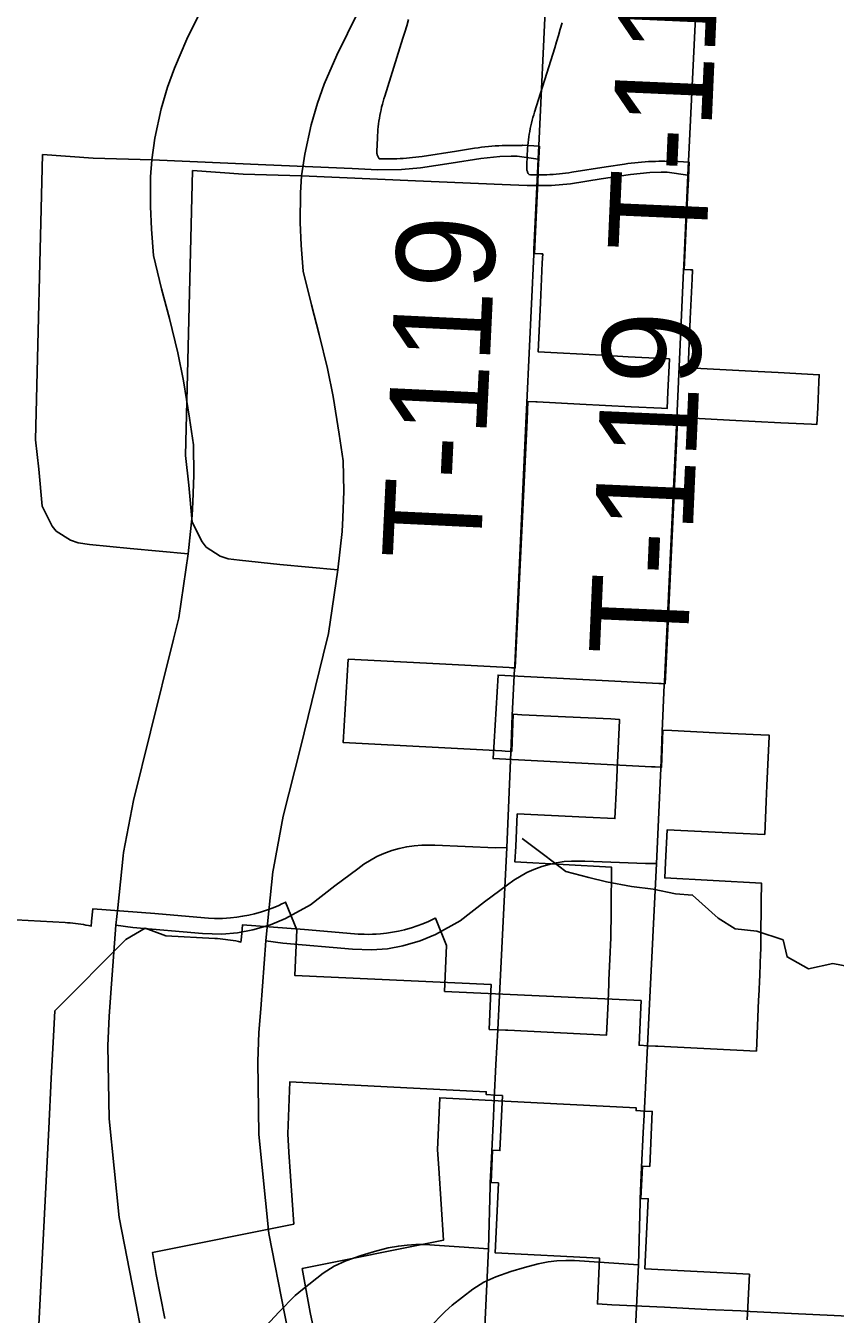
# Model space of a CAD drawing. Extents: x -38.2 to 41.9, y -4 to 24.9.
# Drawn here: x 6.18 to 6.647, y 16.76 to 17.504 of the extents above; entities that cross this region are included whole.
import ezdxf

# ---------------------------------------------------------------- set-up
doc = ezdxf.new("R2010")
doc.units = 0
for name, color, linetype in [('Default', 7, 'Continuous'), ('GM_X_County_Road', 7, 'Continuous'), ('GM_X_Minor_River', 7, 'Continuous'), ('GM_X_State_Location', 7, 'Continuous'), ('GM_X_Township_Road', 7, 'Continuous'), ('GM_X_Township_Road_Text', 7, 'Continuous')]:
    doc.layers.add(name, color=color, linetype=linetype)

msp = doc.modelspace()

# ---------------------------------------------------------------- linework, layer by layer
at = {"layer": 'Default'}
for points in [[(6.4011, 17.5072), (6.40004, 17.5036), (6.39895, 17.50001), (6.39783, 17.49642), (6.38727, 17.46302), (6.38679, 17.46145), (6.38633, 17.45987), (6.38591, 17.45829), (6.38551, 17.45669), (6.38514, 17.45509), (6.3848, 17.45348), (6.38449, 17.45187), (6.38421, 17.45025), (6.38395, 17.44863), (6.38373, 17.447), (6.38353, 17.44537), (6.38337, 17.44373), (6.38323, 17.4421), (6.38312, 17.44046), (6.38304, 17.43882), (6.38274, 17.43124), (6.38274, 17.43081), (6.38282, 17.42997), (6.38289, 17.42955), (6.383, 17.42914), (6.38313, 17.42874), (6.38329, 17.42835), (6.38347, 17.42796), (6.38368, 17.42759), (6.38391, 17.42724), (6.38417, 17.4269), (6.38489, 17.42687), (6.38566, 17.42684), (6.38667, 17.42681), (6.38697, 17.42681), (6.3888, 17.42678), (6.39063, 17.42678), (6.39246, 17.4268), (6.39428, 17.42686), (6.39611, 17.42694), (6.39794, 17.42704), (6.39977, 17.42718), (6.40159, 17.42734), (6.40341, 17.42753), (6.40523, 17.42774), (6.40704, 17.42798), (6.40885, 17.42825), (6.42869, 17.43134), (6.43917, 17.43297), (6.44114, 17.43326), (6.44313, 17.43352), (6.44511, 17.43376), (6.4471, 17.43397), (6.44909, 17.43414), (6.45108, 17.43429), (6.45308, 17.43441), (6.45511, 17.43451), (6.45706, 17.43457), (6.45901, 17.4346), (6.46097, 17.43461), (6.46249, 17.43459), (6.46401, 17.43456), (6.46553, 17.43452), (6.46612, 17.43452), (6.46647, 17.43456), (6.46682, 17.43462), (6.47659, 17.43407), (6.47592, 17.42038), (6.4758, 17.41788), (6.47373, 17.37214), (6.4773, 17.37197), (6.47849, 17.37191), (6.47825, 17.36678), (6.47719, 17.34373), (6.47587, 17.31541), (6.51257, 17.31345), (6.52789, 17.31263), (6.5516, 17.31136), (6.55142, 17.30741), (6.55073, 17.29228), (6.55028, 17.2827), (6.54709, 17.28286), (6.52945, 17.28375), (6.49984, 17.28526), (6.47522, 17.28651), (6.47455, 17.28654), (6.46984, 17.28677), (6.46949, 17.27591), (6.46359, 17.15262), (6.46266, 17.13303), (6.46045, 17.13315), (6.45911, 17.13322), (6.41898, 17.1353), (6.36626, 17.13805), (6.36338, 17.08992), (6.4548, 17.08515), (6.45684, 17.08504), (6.46063, 17.08486), (6.46141, 17.10628), (6.46647, 17.10604), (6.49171, 17.10482), (6.51782, 17.10356), (6.52279, 17.10332), (6.52277, 17.10265), (6.52145, 17.07431), (6.52103, 17.06503), (6.52013, 17.0461), (6.50344, 17.04688), (6.46381, 17.04875), (6.46287, 17.02992), (6.46242, 17.02102), (6.51824, 17.01799), (6.5182, 17.01606), (6.5181, 17.00927), (6.51805, 17.00295), (6.51794, 16.99011), (6.51785, 16.97947), (6.51776, 16.97733), (6.51724, 16.96503), (6.51671, 16.95273), (6.51663, 16.95074), (6.51619, 16.94043), (6.51538, 16.9211), (6.45835, 16.92388), (6.45702, 16.92395), (6.45282, 16.92416), (6.44759, 16.92442), (6.44841, 16.94221), (6.44878, 16.95027), (6.33531, 16.95552), (6.3365, 16.98194), (6.3301, 16.99786), (6.32985, 16.99773), (6.32798, 16.99681), (6.32609, 16.99595), (6.32286, 16.99459), (6.31958, 16.99337), (6.31617, 16.99225), (6.31418, 16.99166), (6.31217, 16.99113), (6.30876, 16.99033), (6.30523, 16.98966), (6.30186, 16.98916), (6.29829, 16.98878), (6.29594, 16.98861), (6.29367, 16.9885), (6.29131, 16.98845), (6.28904, 16.98847), (6.28554, 16.9886), (6.28327, 16.98877), (6.25459, 16.99125), (6.21876, 16.99396), (6.21807, 16.98684), (6.21806, 16.98673), (6.21785, 16.984), (6.21636, 16.98433), (6.21486, 16.98462), (6.21336, 16.9849), (6.21185, 16.98514), (6.21035, 16.98537), (6.20883, 16.98556), (6.20732, 16.98573), (6.2058, 16.98588), (6.20428, 16.986), (6.20276, 16.9861), (6.17446, 16.98766)], [(6.26046, 16.75758), (6.25783, 16.7702), (6.25541, 16.78287), (6.25322, 16.79558), (6.3348, 16.81201), (6.33203, 16.85352), (6.33133, 16.86406), (6.33255, 16.89416), (6.38877, 16.89131), (6.44592, 16.8884), (6.44584, 16.88674), (6.45097, 16.88638), (6.45526, 16.88625), (6.45377, 16.85449), (6.4495, 16.85466), (6.44864, 16.836), (6.4529, 16.83583), (6.45099, 16.7955), (6.51131, 16.79232), (6.51004, 16.76594), (6.51828, 16.76554), (6.54876, 16.76405), (6.57343, 16.76284), (6.59281, 16.7619), (6.5983, 16.76164), (6.62216, 16.76046), (6.65904, 16.75865)]]:
    msp.add_lwpolyline(points, dxfattribs=at)
at = {"layer": 'GM_X_County_Road'}
msp.add_line((6.2332, 16.99461), (6.23633, 17.02451), dxfattribs=at)
for points in [[(6.25266, 17.38627), (6.25205, 17.39928), (6.25218, 17.41636), (6.25285, 17.42619), (6.25463, 17.43869), (6.2583, 17.45571), (6.26194, 17.46813), (6.26586, 17.47906), (6.27308, 17.49584), (6.29189, 17.534), (6.30032, 17.55114), (6.30735, 17.56923), (6.31286, 17.58585), (6.31933, 17.61572), (6.32109, 17.63065), (6.32442, 17.69189)], [(6.48962, 17.50524), (6.48861, 17.50162), (6.48758, 17.49801), (6.48652, 17.49441), (6.48543, 17.49082), (6.48431, 17.48723), (6.47375, 17.45383), (6.47326, 17.45226), (6.47281, 17.45068), (6.47239, 17.4491), (6.47199, 17.4475), (6.47162, 17.4459), (6.47128, 17.44429), (6.47097, 17.44268), (6.47069, 17.44106), (6.47043, 17.43944), (6.47021, 17.43781), (6.47001, 17.43618), (6.46984, 17.43454), (6.46971, 17.43291), (6.4696, 17.43127), (6.46952, 17.42963), (6.46922, 17.42205), (6.46922, 17.42162), (6.46929, 17.42078), (6.46937, 17.42036), (6.46948, 17.41995), (6.46961, 17.41955), (6.46977, 17.41916), (6.46995, 17.41877), (6.47016, 17.41841), (6.47039, 17.41805), (6.47065, 17.41771), (6.47137, 17.41768), (6.47214, 17.41765), (6.47315, 17.41762), (6.47344, 17.41762), (6.47527, 17.41759), (6.4771, 17.41759), (6.47893, 17.41761), (6.48076, 17.41767), (6.48259, 17.41775), (6.48442, 17.41785), (6.48624, 17.41799), (6.48807, 17.41815), (6.48989, 17.41834), (6.4917, 17.41855), (6.49352, 17.41879), (6.49533, 17.41906), (6.51516, 17.42215), (6.52565, 17.42378), (6.52762, 17.42407), (6.5296, 17.42433), (6.53159, 17.42457), (6.53358, 17.42478), (6.53557, 17.42495), (6.53756, 17.4251), (6.53955, 17.42522), (6.54159, 17.42532), (6.54354, 17.42538), (6.54549, 17.42541), (6.54745, 17.42542), (6.54897, 17.4254), (6.55049, 17.42537), (6.55201, 17.42533), (6.55259, 17.42533), (6.55295, 17.42537), (6.5533, 17.42543), (6.56307, 17.42488), (6.5624, 17.41119), (6.56228, 17.40869), (6.56021, 17.36295), (6.56378, 17.36278), (6.56496, 17.36272), (6.56473, 17.35759), (6.56367, 17.33454), (6.56235, 17.30622), (6.59905, 17.30426), (6.61436, 17.30344), (6.63808, 17.30218), (6.63789, 17.29822), (6.63721, 17.28309), (6.63676, 17.27351), (6.63357, 17.27367), (6.61593, 17.27456), (6.58631, 17.27607), (6.56169, 17.27732), (6.56103, 17.27735), (6.55632, 17.27758), (6.55597, 17.26672), (6.55007, 17.14343), (6.54913, 17.12384), (6.54693, 17.12396), (6.54558, 17.12403), (6.50546, 17.12611), (6.45274, 17.12886), (6.44986, 17.08073), (6.54127, 17.07596), (6.54332, 17.07585), (6.54711, 17.07567), (6.54789, 17.09709), (6.55295, 17.09685), (6.57819, 17.09563), (6.6043, 17.09437), (6.60927, 17.09413), (6.60925, 17.09346), (6.60793, 17.06512), (6.60751, 17.05584), (6.60661, 17.03691), (6.58992, 17.0377), (6.55029, 17.03956), (6.54935, 17.02073), (6.5489, 17.01183), (6.60472, 17.0088), (6.60468, 17.00687), (6.60458, 17.00008), (6.60453, 16.99376), (6.60442, 16.98092), (6.60433, 16.97028), (6.60424, 16.96814), (6.60371, 16.95584), (6.60319, 16.94354), (6.6031, 16.94155), (6.60267, 16.93124), (6.60186, 16.91191), (6.54483, 16.91469), (6.5435, 16.91476), (6.5393, 16.91497), (6.53406, 16.91523), (6.53489, 16.93302), (6.53526, 16.94108), (6.42179, 16.94633), (6.42298, 16.97275), (6.41658, 16.98867), (6.41632, 16.98854), (6.41445, 16.98763), (6.41256, 16.98676), (6.40934, 16.9854), (6.40606, 16.98418), (6.40265, 16.98306), (6.40065, 16.98247), (6.39864, 16.98194), (6.39524, 16.98114), (6.39171, 16.98047), (6.38834, 16.97997), (6.38477, 16.97959), (6.38241, 16.97942), (6.38015, 16.97931), (6.37778, 16.97926), (6.37551, 16.97928), (6.37202, 16.97942), (6.36975, 16.97958), (6.34107, 16.98206), (6.30523, 16.98477), (6.30455, 16.97765), (6.30454, 16.97754), (6.30433, 16.97482), (6.30283, 16.97514), (6.30134, 16.97543), (6.29984, 16.97571), (6.29833, 16.97595), (6.29682, 16.97618), (6.29531, 16.97637), (6.29379, 16.97655), (6.29228, 16.97669), (6.29076, 16.97681), (6.28923, 16.97691), (6.26094, 16.97847), (6.24905, 16.98276), (6.23791, 16.97628), (6.1968, 16.93505), (6.19607, 16.92044), (6.19485, 16.89616), (6.19339, 16.86729), (6.19282, 16.85594), (6.19225, 16.84459), (6.19169, 16.83324), (6.19112, 16.82189), (6.19056, 16.81054), (6.18997, 16.7992), (6.1894, 16.78784), (6.18865, 16.77271), (6.18712, 16.74245)], [(6.27655, 17.22875), (6.27719, 17.24425), (6.27687, 17.26168), (6.27461, 17.27717), (6.27106, 17.2988), (6.26783, 17.31493), (6.26299, 17.33462), (6.25847, 17.35173), (6.25379, 17.3711), (6.25266, 17.38627)], [(6.26536, 17.1496), (6.26844, 17.16201), (6.27382, 17.19885), (6.27622, 17.22101), (6.27655, 17.22875)], [(6.23633, 17.02451), (6.23654, 17.0265), (6.24224, 17.05655), (6.25213, 17.09613), (6.26536, 17.1496)], [(6.22922, 16.9455), (6.23216, 16.98464), (6.2332, 16.99461)], [(6.24298, 16.76954), (6.23395, 16.8158), (6.22818, 16.87285), (6.22752, 16.91504), (6.22819, 16.9318), (6.22922, 16.9455)], [(6.34694, 16.74839), (6.3443, 16.76101), (6.34189, 16.77368), (6.3397, 16.78639), (6.42128, 16.80282), (6.41851, 16.84433), (6.41781, 16.85487), (6.41903, 16.88497), (6.47524, 16.88212), (6.5324, 16.87921), (6.53232, 16.87755), (6.53745, 16.87719), (6.54173, 16.87706), (6.54025, 16.8453), (6.53598, 16.84547), (6.53512, 16.82681), (6.53938, 16.82664), (6.53747, 16.78631), (6.59779, 16.78313), (6.59652, 16.75675)], [(6.25351, 16.7211), (6.24712, 16.74833), (6.24298, 16.76954)]]:
    msp.add_lwpolyline(points, dxfattribs=at)
at = {"layer": 'GM_X_Minor_River'}
msp.add_lwpolyline([(6.65997, 16.95973), (6.64597, 16.9624), (6.63197, 16.95937), (6.61948, 16.9662), (6.6172, 16.97607), (6.60206, 16.98101), (6.58957, 16.98253), (6.57973, 16.9886), (6.56496, 17.00189), (6.55512, 17.00265), (6.54225, 17.00532), (6.52976, 17.00684), (6.51538, 17.0095), (6.50516, 17.01216), (6.49191, 17.01558), (6.47979, 17.02469), (6.46654, 17.03456)], dxfattribs=at)
at = {"layer": 'GM_X_State_Location'}
for p, q in [((6.56266, 17.42542), (6.56848, 17.54534)), ((6.54876, 17.12523), (6.5553, 17.265)), ((6.54665, 17.07497), (6.54702, 17.08522)), ((6.53897, 16.91501), (6.53996, 16.93505)), ((6.53799, 16.89497), (6.53897, 16.91501)), ((6.537, 16.87493), (6.53799, 16.89497)), ((6.53651, 16.86491), (6.537, 16.87493)), ((6.53552, 16.84487), (6.53651, 16.86491))]:
    msp.add_line(p, q, dxfattribs=at)
for points in [[(6.55988, 17.36535), (6.56227, 17.41742), (6.56266, 17.42542)], [(6.3603, 17.18967), (6.32677, 17.19279), (6.30338, 17.19512), (6.29683, 17.19606), (6.29231, 17.19761), (6.28422, 17.2028), (6.28185, 17.20572), (6.27607, 17.21718), (6.27415, 17.23851), (6.27223, 17.25552), (6.27628, 17.42008)], [(6.27628, 17.42008), (6.3055, 17.41805), (6.33933, 17.417), (6.40508, 17.41416), (6.45503, 17.412), (6.46954, 17.41138), (6.48353, 17.41142), (6.49444, 17.41246), (6.51216, 17.4152), (6.52919, 17.41785), (6.54024, 17.41894), (6.54681, 17.41913), (6.55029, 17.4191), (6.56227, 17.41742)], [(6.5553, 17.265), (6.55586, 17.27698), (6.55974, 17.36234), (6.55988, 17.36535)], [(6.54702, 17.08522), (6.54742, 17.09649), (6.54867, 17.12323), (6.54876, 17.12523)], [(6.53996, 16.93505), (6.54415, 17.02022), (6.54665, 17.07497)], [(6.41653, 16.97919), (6.4309, 16.9871), (6.44494, 16.99802), (6.45824, 17.00793), (6.46177, 17.01051), (6.4693, 17.01492), (6.47328, 17.01673), (6.47791, 17.01843), (6.48213, 17.01966), (6.48643, 17.02058), (6.49079, 17.02121), (6.49518, 17.02154), (6.50276, 17.02149), (6.53777, 17.02008), (6.54415, 17.02022)], [(6.31864, 16.97545), (6.32841, 16.97408), (6.36866, 16.97065), (6.37968, 16.97025), (6.38881, 16.97097), (6.39767, 16.97264), (6.40783, 16.9756), (6.41653, 16.97919)], [(6.53463, 16.82466), (6.53468, 16.82667), (6.53552, 16.84487)], [(6.52004, 16.52505), (6.52655, 16.63747), (6.53371, 16.7886), (6.53463, 16.82466)], [(6.33998, 16.71191), (6.36432, 16.71795), (6.37121, 16.72012), (6.37571, 16.72193), (6.38009, 16.72401), (6.39216, 16.73093), (6.39764, 16.73661), (6.40534, 16.74417), (6.4127, 16.75194), (6.42217, 16.76156), (6.42623, 16.76518), (6.4382, 16.77449), (6.4445, 16.77859), (6.45138, 16.78162), (6.46016, 16.78469), (6.46792, 16.78704), (6.47576, 16.78911), (6.48165, 16.79018), (6.48672, 16.79076), (6.49181, 16.79104), (6.49691, 16.79103), (6.53371, 16.7886)]]:
    msp.add_lwpolyline(points, dxfattribs=at)
at = {"layer": 'GM_X_Township_Road'}
for p, q in [((6.47618, 17.43461), (6.482, 17.55453)), ((6.46229, 17.13442), (6.46882, 17.27419)), ((6.46017, 17.08416), (6.46054, 17.09441)), ((6.45249, 16.9242), (6.45348, 16.94424)), ((6.45151, 16.90416), (6.45249, 16.9242)), ((6.45052, 16.88412), (6.45151, 16.90416)), ((6.45003, 16.8741), (6.45052, 16.88412)), ((6.44904, 16.85406), (6.45003, 16.8741))]:
    msp.add_line(p, q, dxfattribs=at)
for points in [[(6.4734, 17.37454), (6.47579, 17.42661), (6.47618, 17.43461)], [(6.27382, 17.19885), (6.24029, 17.20198), (6.2169, 17.20431), (6.21035, 17.20525), (6.20583, 17.2068), (6.19774, 17.21199), (6.19538, 17.21491), (6.1896, 17.22637), (6.18767, 17.24769), (6.18575, 17.26471), (6.1898, 17.42927)], [(6.1898, 17.42927), (6.21903, 17.42724), (6.25285, 17.42619), (6.31861, 17.42335), (6.36855, 17.42119), (6.38306, 17.42057), (6.39705, 17.42061), (6.40797, 17.42165), (6.42568, 17.42439), (6.44271, 17.42704), (6.45376, 17.42813), (6.46033, 17.42832), (6.46381, 17.42829), (6.47579, 17.42661)], [(6.46882, 17.27419), (6.46938, 17.28617), (6.47327, 17.37153), (6.4734, 17.37454)], [(6.46054, 17.09441), (6.46094, 17.10568), (6.46219, 17.13242), (6.46229, 17.13442)], [(6.45348, 16.94424), (6.45767, 17.02941), (6.46017, 17.08416)], [(6.33005, 16.98838), (6.34442, 16.99629), (6.35847, 17.00721), (6.37176, 17.01712), (6.37529, 17.0197), (6.38282, 17.02411), (6.3868, 17.02591), (6.39143, 17.02762), (6.39566, 17.02885), (6.39996, 17.02977), (6.40431, 17.0304), (6.4087, 17.03073), (6.41628, 17.03067), (6.45129, 17.02927), (6.45767, 17.02941)], [(6.23216, 16.98464), (6.24194, 16.98327), (6.28218, 16.97984), (6.2932, 16.97944), (6.30233, 16.98016), (6.31119, 16.98183), (6.32135, 16.98479), (6.33005, 16.98838)], [(6.44815, 16.83385), (6.4482, 16.83586), (6.44904, 16.85406)], [(6.43356, 16.53424), (6.44007, 16.64666), (6.44723, 16.79779), (6.44815, 16.83385)], [(6.25351, 16.7211), (6.27784, 16.72714), (6.28473, 16.72931), (6.28923, 16.73112), (6.29361, 16.7332), (6.30568, 16.74012), (6.31116, 16.7458), (6.31887, 16.75336), (6.32622, 16.76113), (6.33569, 16.77075), (6.33975, 16.77437), (6.35173, 16.78368), (6.35802, 16.78777), (6.3649, 16.79081), (6.37368, 16.79388), (6.38144, 16.79623), (6.38928, 16.7983), (6.39517, 16.79937), (6.40024, 16.79995), (6.40533, 16.80023), (6.41043, 16.80021), (6.44723, 16.79779)]]:
    msp.add_lwpolyline(points, dxfattribs=at)
at = {"layer": 'GM_X_Township_Road_Text'}
msp.add_line((6.31968, 16.98542), (6.3228, 17.01532), dxfattribs=at)
for points in [[(6.33914, 17.37708), (6.33853, 17.39009), (6.33865, 17.40717), (6.33933, 17.417), (6.34111, 17.4295), (6.34478, 17.44652), (6.34841, 17.45894), (6.35234, 17.46987), (6.35956, 17.48666), (6.37836, 17.52481), (6.3868, 17.54195), (6.39382, 17.56005), (6.39934, 17.57666), (6.40581, 17.60653), (6.40756, 17.62146), (6.41089, 17.6827)], [(6.36302, 17.21956), (6.36367, 17.23506), (6.36335, 17.25249), (6.36108, 17.26798), (6.35754, 17.28961), (6.35431, 17.30574), (6.34946, 17.32543), (6.34495, 17.34254), (6.34027, 17.36191), (6.33914, 17.37708)], [(6.35184, 17.14041), (6.35491, 17.15282), (6.3603, 17.18967), (6.3627, 17.21182), (6.36302, 17.21956)], [(6.3228, 17.01532), (6.32301, 17.01731), (6.32872, 17.04737), (6.33861, 17.08694), (6.35184, 17.14041)], [(6.3157, 16.93631), (6.31864, 16.97545), (6.31968, 16.98542)], [(6.32946, 16.76035), (6.32043, 16.80662), (6.31466, 16.86366), (6.314, 16.90585), (6.31467, 16.92261), (6.3157, 16.93631)], [(6.33998, 16.71191), (6.3336, 16.73914), (6.32946, 16.76035)]]:
    msp.add_lwpolyline(points, dxfattribs=at)

# ---------------------------------------------------------------- texts
for rotation, p in [(87.47364, (6.57272, 17.37221)), (87.26432, (6.44242, 17.19437)), (87.47836, (6.5619, 17.13916))]:
    msp.add_text('T-119', height=0.056818, rotation=rotation, dxfattribs=at).set_placement(p)

doc.saveas('drawing.dxf')
